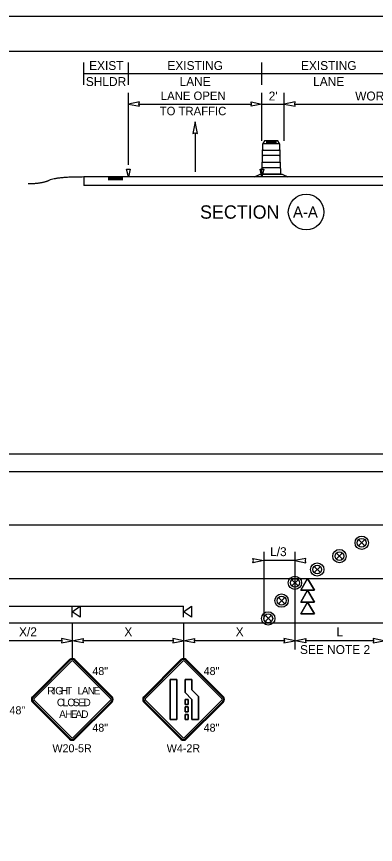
# Model space of a CAD drawing. Extents: x 99958 to 100136, y 99935 to 100013.
# Drawn here: x 100004.27 to 100007.5, y 100003.24 to 100010.69 of the extents above; entities that cross this region are included whole.
import ezdxf

# ---------------------------------------------------------------- set-up
doc = ezdxf.new("R2010")
doc.units = 0
for name, color, linetype in [('RD_ED_ShoulderPavedEdge', 7, 'Continuous'), ('RD_MK_LineEdgeWhite', 7, 'Continuous'), ('RD_MK_LineEdgeYellow', 7, 'Continuous'), ('RD_MK_LineLane', 7, 'Continuous'), ('SH_GI_PlotLimits', 7, 'Continuous'), ('SH_GI_SheetBorder', 7, 'Continuous'), ('SH_TI_WZSectionCut', 7, 'Continuous'), ('TR_SN_ConstructionSigns', 7, 'Continuous'), ('TR_WZ_ArrowLeftStrRightTurn', 7, 'Continuous'), ('TR_WZ_PortableSignMountBlk-Org', 7, 'Continuous'), ('TR_WZ_SequentialArrowSign', 7, 'Continuous'), ('TR_WZ_TrafficSafetyDrum', 7, 'Continuous'), ('TR_WZ_TrafficSafetyDrumElev', 7, 'Continuous'), ('TR_WZ_WorkZoneDetails', 7, 'Continuous'), ('TR_WZ_WorkZoneTextCurrent', 7, 'Continuous')]:
    doc.layers.add(name, color=color, linetype=linetype)

msp = doc.modelspace()

# ---------------------------------------------------------------- linework, layer by layer
at = {"layer": 'RD_ED_ShoulderPavedEdge'}
for p, q in [((100000.8283, 100006.7557), (100015.62, 100006.7557)), ((100000.8283, 100005.2357), (100015.62, 100005.2357))]:
    msp.add_line(p, q, dxfattribs=at)
at = {"layer": 'RD_MK_LineEdgeWhite'}
msp.add_line((100000.8283, 100005.6357), (100015.62, 100005.6357), dxfattribs=at)
at = {"layer": 'RD_MK_LineEdgeYellow'}
msp.add_line((100000.8283, 100006.5957), (100015.62, 100006.5957), dxfattribs=at)
at = {"layer": 'RD_MK_LineLane'}
msp.add_lwpolyline([(100015.62, 100006.1157), (100000.8283, 100006.1157)], dxfattribs=at)
at = {"layer": 'SH_GI_PlotLimits'}
msp.add_lwpolyline([(99999.0625, 99999.6875), (100016.0625, 99999.6875), (100016.0625, 100010.6875), (99999.0625, 100010.6875)], close=True, dxfattribs=at)
at = {"layer": 'SH_GI_SheetBorder'}
msp.add_line((100000, 100010.375), (100015.75, 100010.375), dxfattribs=at)
at = {"layer": 'SH_TI_WZSectionCut'}
for p, q in [((100004.8794, 100010.075), (100004.8794, 100010.275)), ((100005.2794, 100010.075), (100005.2794, 100010.275)), ((100006.4794, 100010.075), (100006.4794, 100010.275)), ((100004.8794, 100010.175), (100005.2794, 100010.175)), ((100005.2794, 100010.175), (100006.4794, 100010.175)), ((100006.4794, 100010.175), (100007.6794, 100010.175)), ((100005.2794, 100009.3547), (100005.2794, 100010.001)), ((100006.4794, 100009.57), (100006.4794, 100010.001)), ((100006.6794, 100009.57), (100006.6794, 100010.001)), ((100005.3731, 100009.901), (100006.3857, 100009.901)), ((100006.4794, 100009.901), (100006.6794, 100009.901)), ((100006.7731, 100009.901), (100008.5857, 100009.901)), ((100004.8794, 100009.2449), (100004.8794, 100009.1699)), ((100008.6794, 100009.2449), (100004.8794, 100009.2449)), ((100005.0964, 100009.2397), (100005.2294, 100009.2397)), ((100005.0964, 100009.2341), (100005.2294, 100009.2341)), ((100005.0964, 100009.2284), (100005.2294, 100009.2284)), ((100005.0964, 100009.2232), (100005.2294, 100009.2232)), ((100008.6794, 100009.1699), (100004.8794, 100009.1699))]:
    msp.add_line(p, q, dxfattribs=at)
for points in [[(100005.2794, 100009.901), (100005.3777, 100009.8817), (100005.3731, 100009.901), (100005.3777, 100009.9203)], [(100006.4794, 100009.901), (100006.3811, 100009.8817), (100006.3857, 100009.901), (100006.3811, 100009.9203)], [(100006.6794, 100009.901), (100006.7777, 100009.8817), (100006.7731, 100009.901), (100006.7777, 100009.9203)], [(100005.2627, 100009.3147), (100005.296, 100009.3147), (100005.2794, 100009.2449)], [(100006.4627, 100009.3147), (100006.4961, 100009.3147), (100006.4794, 100009.2449)]]:
    msp.add_lwpolyline(points, close=True, dxfattribs=at)
msp.add_circle((100006.8759, 100008.93), 0.16, dxfattribs=at)
msp.add_open_spline([(100004.8794, 100009.2449), (100004.6282, 100009.2449), (100004.5027, 100009.1828), (100004.3773, 100009.1828)], degree=2, dxfattribs=at)
at = {"layer": 'TR_SN_ConstructionSigns'}
for p, q in [((100004.7514, 100004.9058), (100004.4173, 100004.5717)), ((100004.7574, 100004.8999), (100004.4233, 100004.5658)), ((100005.1273, 100004.5658), (100004.7932, 100004.8999)), ((100005.1333, 100004.5717), (100004.7991, 100004.9058)), ((100005.7514, 100004.9058), (100005.4173, 100004.5717)), ((100005.7574, 100004.8999), (100005.4233, 100004.5658)), ((100006.1273, 100004.5658), (100005.7932, 100004.8999)), ((100006.1333, 100004.5717), (100005.7991, 100004.9058)), ((100004.4332, 100004.5558), (100004.7673, 100004.8899)), ((100004.7832, 100004.8899), (100005.1173, 100004.5558)), ((100005.4332, 100004.5558), (100005.7673, 100004.8899)), ((100005.7832, 100004.8899), (100006.1173, 100004.5558)), ((100005.6536, 100004.7279), (100005.7141, 100004.7279)), ((100005.6536, 100004.3679), (100005.6536, 100004.7279)), ((100005.7141, 100004.7279), (100005.6536, 100004.7279)), ((100005.6536, 100004.7279), (100005.6536, 100004.3679)), ((100005.7141, 100004.7279), (100005.7141, 100004.3679)), ((100005.7141, 100004.3679), (100005.7141, 100004.7279)), ((100005.7893, 100004.7279), (100005.8498, 100004.7279)), ((100005.7893, 100004.6083), (100005.7893, 100004.7279)), ((100005.8498, 100004.7279), (100005.7893, 100004.7279)), ((100005.7893, 100004.7279), (100005.7893, 100004.6083)), ((100005.8498, 100004.7279), (100005.8498, 100004.6334)), ((100005.8498, 100004.6334), (100005.8498, 100004.7279)), ((100005.8498, 100004.5479), (100005.7893, 100004.6083)), ((100005.7893, 100004.6083), (100005.8498, 100004.5479)), ((100005.8498, 100004.6334), (100005.9103, 100004.5729)), ((100005.9103, 100004.5729), (100005.8498, 100004.6334)), ((100004.4173, 100004.524), (100004.7514, 100004.1899)), ((100004.4233, 100004.53), (100004.7574, 100004.1959)), ((100004.7673, 100004.2058), (100004.4332, 100004.5399)), ((100005.1173, 100004.5399), (100004.7832, 100004.2058)), ((100004.7932, 100004.1959), (100005.1273, 100004.53)), ((100004.7991, 100004.1899), (100005.1333, 100004.524)), ((100005.4173, 100004.524), (100005.7514, 100004.1899)), ((100005.4233, 100004.53), (100005.7574, 100004.1959)), ((100005.7673, 100004.2058), (100005.4332, 100004.5399)), ((100006.1173, 100004.5399), (100005.7832, 100004.2058)), ((100005.7893, 100004.5479), (100005.8161, 100004.5479)), ((100005.7893, 100004.5029), (100005.7893, 100004.5479)), ((100005.8161, 100004.5479), (100005.7893, 100004.5479)), ((100005.7893, 100004.5479), (100005.7893, 100004.5029)), ((100005.7932, 100004.1959), (100006.1273, 100004.53)), ((100005.7991, 100004.1899), (100006.1333, 100004.524)), ((100005.8161, 100004.5479), (100005.8161, 100004.5029)), ((100005.8161, 100004.5029), (100005.8161, 100004.5479)), ((100005.8498, 100004.3679), (100005.8498, 100004.5479)), ((100005.8498, 100004.5479), (100005.8498, 100004.3679)), ((100005.9103, 100004.5729), (100005.9103, 100004.3679)), ((100005.9103, 100004.3679), (100005.9103, 100004.5729)), ((100005.8161, 100004.5029), (100005.7893, 100004.5029)), ((100005.7893, 100004.5029), (100005.8161, 100004.5029)), ((100005.7893, 100004.4804), (100005.8161, 100004.4804)), ((100005.7893, 100004.4354), (100005.7893, 100004.4804)), ((100005.8161, 100004.4804), (100005.7893, 100004.4804)), ((100005.7893, 100004.4804), (100005.7893, 100004.4354)), ((100005.8161, 100004.4804), (100005.8161, 100004.4354)), ((100005.8161, 100004.4354), (100005.8161, 100004.4804)), ((100005.8161, 100004.4354), (100005.7893, 100004.4354)), ((100005.7893, 100004.4354), (100005.8161, 100004.4354)), ((100005.7893, 100004.4129), (100005.8161, 100004.4129)), ((100005.7893, 100004.3679), (100005.7893, 100004.4129)), ((100005.8161, 100004.4129), (100005.7893, 100004.4129)), ((100005.7893, 100004.4129), (100005.7893, 100004.3679)), ((100005.8161, 100004.4129), (100005.8161, 100004.3679)), ((100005.8161, 100004.3679), (100005.8161, 100004.4129)), ((100005.7141, 100004.3679), (100005.6536, 100004.3679)), ((100005.6536, 100004.3679), (100005.7141, 100004.3679)), ((100005.8161, 100004.3679), (100005.7893, 100004.3679)), ((100005.7893, 100004.3679), (100005.8161, 100004.3679)), ((100005.9103, 100004.3679), (100005.8498, 100004.3679)), ((100005.8498, 100004.3679), (100005.9103, 100004.3679))]:
    msp.add_line(p, q, dxfattribs=at)
for centre, radius, start, end in [((100004.7753, 100004.882), 0.0338, 45, 135), ((100004.7753, 100004.882), 0.0253, 45, 135), ((100004.7753, 100004.882), 0.0113, 45, 135), ((100005.7753, 100004.882), 0.0338, 45, 135), ((100005.7753, 100004.882), 0.0253, 45, 135), ((100005.7753, 100004.882), 0.0113, 45, 135), ((100004.4412, 100004.5479), 0.0338, 135, 225.00001), ((100004.4412, 100004.5479), 0.0253, 135, 225.00001), ((100004.4412, 100004.5479), 0.0113, 135, 225.00001), ((100005.1094, 100004.5479), 0.0113, 315.00002, 45), ((100005.1094, 100004.5479), 0.0253, 315.00002, 45), ((100005.1094, 100004.5479), 0.0338, 315.00001, 45.00001), ((100005.4412, 100004.5479), 0.0338, 135, 225.00001), ((100005.4412, 100004.5479), 0.0253, 135, 225.00001), ((100005.4412, 100004.5479), 0.0113, 135, 225.00001), ((100006.1094, 100004.5479), 0.0113, 315.00002, 45), ((100006.1094, 100004.5479), 0.0253, 315.00002, 45), ((100006.1094, 100004.5479), 0.0338, 315.00001, 45.00001), ((100004.7753, 100004.2138), 0.0338, 225.00001, 315.00001), ((100004.7753, 100004.2138), 0.0253, 225.00001, 315.00002), ((100004.7753, 100004.2138), 0.0113, 225.00001, 315.00002), ((100005.7753, 100004.2138), 0.0338, 225.00001, 315.00001), ((100005.7753, 100004.2138), 0.0253, 225.00001, 315.00002), ((100005.7753, 100004.2138), 0.0113, 225.00001, 315.00002)]:
    msp.add_arc(centre, radius, start, end, dxfattribs=at)
at = {"layer": 'TR_WZ_ArrowLeftStrRightTurn'}
msp.add_line((100005.8794, 100009.6418), (100005.8794, 100009.292), dxfattribs=at)
msp.add_lwpolyline([(100005.8794, 100009.742), (100005.8588, 100009.6369), (100005.8794, 100009.6418), (100005.9, 100009.6369)], close=True, dxfattribs=at)
at = {"layer": 'TR_WZ_PortableSignMountBlk-Org'}
for p, q in [((100004.7753, 100005.2858), (100004.7753, 100005.3858)), ((100005.7753, 100005.2858), (100005.7753, 100005.3858))]:
    msp.add_line(p, q, dxfattribs=at)
for points in [[(100004.7753, 100005.3357), (100004.8471, 100005.3858), (100004.8471, 100005.2858)], [(100005.7753, 100005.3357), (100005.8471, 100005.3858), (100005.8471, 100005.2858)]]:
    msp.add_lwpolyline(points, close=True, dxfattribs=at)
at = {"layer": 'TR_WZ_SequentialArrowSign'}
for points in [[(100006.8895, 100005.6357), (100006.8278, 100005.5291), (100006.8895, 100005.5291), (100006.9513, 100005.5291), (100006.8895, 100005.6357)], [(100006.9513, 100005.5291), (100006.8895, 100005.5291), (100006.8278, 100005.5291), (100006.8895, 100005.6357), (100006.9513, 100005.5291)], [(100006.8895, 100005.5291), (100006.8278, 100005.4224), (100006.8895, 100005.4224), (100006.9513, 100005.4224), (100006.8895, 100005.5291)], [(100006.9513, 100005.4224), (100006.8895, 100005.4224), (100006.8278, 100005.4224), (100006.8895, 100005.5291), (100006.9513, 100005.4224)], [(100006.8895, 100005.4224), (100006.8278, 100005.3157), (100006.9513, 100005.3157), (100006.8895, 100005.4224)], [(100006.9513, 100005.3157), (100006.8278, 100005.3157), (100006.8895, 100005.4224), (100006.9513, 100005.3157)]]:
    msp.add_lwpolyline(points, dxfattribs=at)
at = {"layer": 'TR_WZ_TrafficSafetyDrum'}
for p, q in [((100007.347, 100005.984), (100007.4036, 100005.9274)), ((100007.4036, 100005.984), (100007.347, 100005.9274)), ((100007.147, 100005.864), (100007.2036, 100005.8074)), ((100007.2036, 100005.864), (100007.147, 100005.8074)), ((100006.947, 100005.744), (100007.0036, 100005.6874)), ((100007.0036, 100005.744), (100006.947, 100005.6874)), ((100006.747, 100005.624), (100006.8036, 100005.5674)), ((100006.8036, 100005.624), (100006.747, 100005.5674)), ((100006.627, 100005.464), (100006.6836, 100005.4074)), ((100006.6836, 100005.464), (100006.627, 100005.4074)), ((100006.507, 100005.304), (100006.5636, 100005.2474)), ((100006.5636, 100005.304), (100006.507, 100005.2474))]:
    msp.add_line(p, q, dxfattribs=at)
for centre, radius in [((100007.3753, 100005.9557), 0.06), ((100007.3753, 100005.9557), 0.06), ((100007.3753, 100005.9557), 0.04), ((100007.1753, 100005.8357), 0.06), ((100007.1753, 100005.8357), 0.06), ((100007.1753, 100005.8357), 0.04), ((100006.9753, 100005.7157), 0.06), ((100006.9753, 100005.7157), 0.06), ((100006.9753, 100005.7157), 0.04), ((100006.7753, 100005.5957), 0.06), ((100006.7753, 100005.5957), 0.06), ((100006.7753, 100005.5957), 0.04), ((100006.6553, 100005.4357), 0.06), ((100006.6553, 100005.4357), 0.06), ((100006.6553, 100005.4357), 0.04), ((100006.5353, 100005.2757), 0.06), ((100006.5353, 100005.2757), 0.06), ((100006.5353, 100005.2757), 0.04)]:
    msp.add_circle(centre, radius, dxfattribs=at)
at = {"layer": 'TR_WZ_TrafficSafetyDrumElev'}
for p, q in [((100006.4878, 100009.545), (100006.6358, 100009.545)), ((100006.4878, 100009.545), (100006.6358, 100009.545)), ((100006.5222, 100009.564), (100006.604, 100009.564)), ((100006.604, 100009.551), (100006.5222, 100009.551)), ((100006.4849, 100009.4871), (100006.6386, 100009.4871)), ((100006.4849, 100009.4372), (100006.4849, 100009.4871)), ((100006.6386, 100009.4372), (100006.4849, 100009.4372)), ((100006.6386, 100009.4871), (100006.6386, 100009.4372)), ((100006.4812, 100009.377), (100006.6423, 100009.377)), ((100006.4812, 100009.3271), (100006.4812, 100009.377)), ((100006.6423, 100009.377), (100006.6423, 100009.3271)), ((100006.6423, 100009.3271), (100006.4812, 100009.3271))]:
    msp.add_line(p, q, dxfattribs=at)
for points in [[(100006.4868, 100009.4915), (100006.4868, 100009.543)], [(100006.4868, 100009.4915), (100006.4868, 100009.543)], [(100006.6368, 100009.543), (100006.6368, 100009.4915)], [(100006.6368, 100009.543), (100006.6368, 100009.4915)], [(100006.4831, 100009.3814), (100006.4831, 100009.4327)], [(100006.4831, 100009.3814), (100006.4831, 100009.4327)], [(100006.4849, 100009.4365), (100006.4849, 100009.4878)], [(100006.4849, 100009.4365), (100006.4849, 100009.4878)], [(100006.6386, 100009.4878), (100006.6386, 100009.4365)], [(100006.6386, 100009.4878), (100006.6386, 100009.4365)], [(100006.6405, 100009.4327), (100006.6405, 100009.3814)], [(100006.6405, 100009.4327), (100006.6405, 100009.3814)], [(100006.4812, 100009.3264), (100006.4812, 100009.3777)], [(100006.4812, 100009.3264), (100006.4812, 100009.3777)], [(100006.6423, 100009.3777), (100006.6423, 100009.3264)], [(100006.6423, 100009.3777), (100006.6423, 100009.3264)], [(100006.6442, 100009.3226), (100006.6442, 100009.27), (100006.4794, 100009.27), (100006.4794, 100009.3226)], [(100006.6442, 100009.3226), (100006.6442, 100009.27), (100006.4794, 100009.27), (100006.4794, 100009.3226)]]:
    msp.add_lwpolyline(points, dxfattribs=at)
for points in [[(100006.6358, 100009.545), (100006.6226, 100009.57), (100006.5009, 100009.57), (100006.4878, 100009.545)], [(100006.4118, 100009.245), (100006.462, 100009.27), (100006.6615, 100009.27), (100006.7118, 100009.245)]]:
    msp.add_lwpolyline(points, close=True, dxfattribs=at)
for centre, major_axis, ratio, start_param, end_param in [((100006.488, 100009.5426), (0, 0.00249), 0.493438, 0.177149, 1.393647), ((100006.488, 100009.5426), (0, 0.00249), 0.493438, 0.177149, 1.393647), ((100006.5222, 100009.5575), (0, 0.0065), 0.570305, 0, 3.141593), ((100006.604, 100009.5575), (0, 0.0065), 0.570305, 3.141593, 6.283185), ((100006.6356, 100009.5426), (0, 0.00249), 0.493438, 4.889538, 6.106036), ((100006.6356, 100009.5426), (0, 0.00249), 0.493438, 4.889538, 6.106036), ((100006.4865, 100009.4296), (0, 0.00758), 0.493438, 0.4288, 1.141997), ((100006.4865, 100009.4296), (0, 0.00758), 0.493438, 0.4288, 1.141997), ((100006.4883, 100009.4846), (0, 0.00758), 0.493438, 0.4288, 1.141997), ((100006.4883, 100009.4846), (0, 0.00758), 0.493438, 0.4288, 1.141997), ((100006.6352, 100009.4846), (0, 0.00758), 0.493438, 5.141189, 5.854386), ((100006.6352, 100009.4846), (0, 0.00758), 0.493438, 5.141189, 5.854386), ((100006.6371, 100009.4296), (0, 0.00758), 0.493438, 5.141189, 5.854386), ((100006.6371, 100009.4296), (0, 0.00758), 0.493438, 5.141189, 5.854386), ((100006.4846, 100009.3745), (0, 0.00758), 0.493438, 0.4288, 1.141997), ((100006.4846, 100009.3745), (0, 0.00758), 0.493438, 0.4288, 1.141997), ((100006.6389, 100009.3745), (0, 0.00758), 0.493438, 5.141189, 5.854386), ((100006.6389, 100009.3745), (0, 0.00758), 0.493438, 5.141189, 5.854386), ((100006.4828, 100009.3195), (0, 0.00758), 0.493438, 0.4288, 1.141997), ((100006.4828, 100009.3195), (0, 0.00758), 0.493438, 0.4288, 1.141997), ((100006.6408, 100009.3195), (0, 0.00758), 0.493438, 5.141189, 5.854386), ((100006.6408, 100009.3195), (0, 0.00758), 0.493438, 5.141189, 5.854386)]:
    msp.add_ellipse(centre, major_axis=major_axis, ratio=ratio, start_param=start_param, end_param=end_param, dxfattribs=at)
at = {"layer": 'TR_WZ_WorkZoneDetails'}
for p, q in [((100006.4953, 100005.8757), (100006.4953, 100005.2757)), ((100006.7753, 100005.8757), (100006.7753, 100004.9957)), ((100006.7753, 100005.7957), (100006.4953, 100005.7957)), ((100003.2471, 100005.3858), (100005.7753, 100005.3858)), ((100004.7753, 100005.236), (100004.7753, 100004.9157)), ((100005.7753, 100005.236), (100005.7753, 100004.9157)), ((100004.6815, 100005.0757), (100004.069, 100005.0757)), ((100005.6815, 100005.0757), (100004.869, 100005.0757)), ((100006.6815, 100005.0757), (100005.869, 100005.0757)), ((100007.4815, 100005.0757), (100006.869, 100005.0757))]:
    msp.add_line(p, q, dxfattribs=at)
for points in [[(100006.4953, 100005.7957), (100006.397, 100005.7765), (100006.4016, 100005.7957), (100006.397, 100005.815)], [(100006.7753, 100005.7957), (100006.8736, 100005.7765), (100006.869, 100005.7957), (100006.8736, 100005.815)], [(100004.7753, 100005.0757), (100004.677, 100005.095), (100004.6815, 100005.0757), (100004.677, 100005.0565)], [(100004.7753, 100005.0757), (100004.8736, 100005.095), (100004.869, 100005.0757), (100004.8736, 100005.0565)], [(100005.7753, 100005.0757), (100005.677, 100005.095), (100005.6815, 100005.0757), (100005.677, 100005.0565)], [(100005.7753, 100005.0757), (100005.8736, 100005.095), (100005.869, 100005.0757), (100005.8736, 100005.0565)], [(100006.7753, 100005.0757), (100006.677, 100005.095), (100006.6815, 100005.0757), (100006.677, 100005.0565)], [(100006.7753, 100005.0757), (100006.8736, 100005.095), (100006.869, 100005.0757), (100006.8736, 100005.0565)], [(100007.5753, 100005.0757), (100007.477, 100005.095), (100007.4815, 100005.0757), (100007.477, 100005.0565)]]:
    msp.add_lwpolyline(points, close=True, dxfattribs=at)

# ---------------------------------------------------------------- texts
at = {"layer": 'SH_TI_WZSectionCut'}
for s, height, p in [('EXIST', 0.08, (100004.9261, 100010.207)), ('EXISTING', 0.08, (100005.6296, 100010.207)), ('EXISTING', 0.08, (100006.8296, 100010.207)), ('SHLDR', 0.08, (100004.8969, 100010.063)), ('LANE', 0.08, (100005.739, 100010.063)), ('LANE', 0.08, (100006.939, 100010.063)), ('SECTION', 0.12, (100005.9229, 100008.87)), ('A-A', 0.1, (100006.7581, 100008.88))]:
    msp.add_text(s, height=height, rotation=360, dxfattribs=at).set_placement(p)
for s, height, p in [('LANE OPEN', 0.076, (100005.5707, 100009.937)), ("2'", 0.08, (100006.5394, 100009.933)), ('WORK AREA', 0.08, (100007.3165, 100009.933)), ('TO TRAFFIC', 0.076, (100005.5606, 100009.8002))]:
    msp.add_text(s, height=height, dxfattribs=at).set_placement(p)
at = {"layer": 'TR_SN_ConstructionSigns'}
for s, p in [('48"', (100004.9551, 100004.7664)), ('48"', (100005.9551, 100004.7664)), ('48"', (100004.211, 100004.414)), ('48"', (100004.9551, 100004.2573)), ('48"', (100005.9551, 100004.2573)), ('W20-5R', (100004.5966, 100004.072)), ('W4-2R', (100005.6238, 100004.072))]:
    msp.add_text(s, height=0.072, rotation=360, dxfattribs=at).set_placement(p)
for s, p in [('R', (100004.5498, 100004.5922)), ('I', (100004.5991, 100004.5922)), ('G', (100004.6221, 100004.5922)), ('H', (100004.6734, 100004.5922)), ('T', (100004.7206, 100004.5922)), ('L', (100004.8225, 100004.5922)), ('A', (100004.861, 100004.5922)), ('N', (100004.9137, 100004.5922)), ('E', (100004.9663, 100004.5922)), ('C', (100004.6369, 100004.4867)), ('L', (100004.6882, 100004.4867)), ('O', (100004.7307, 100004.4867)), ('S', (100004.7807, 100004.4867)), ('E', (100004.83, 100004.4867)), ('D', (100004.8759, 100004.4867)), ('A', (100004.6572, 100004.3812)), ('H', (100004.7098, 100004.3812)), ('E', (100004.7625, 100004.3812)), ('A', (100004.803, 100004.3812)), ('D', (100004.8556, 100004.3812))]:
    msp.add_text(s, height=0.0675, dxfattribs=at).set_placement(p)
at = {"layer": 'TR_WZ_WorkZoneTextCurrent'}
msp.add_text('L/3', height=0.08, dxfattribs=at).set_placement((100006.5521, 100005.8357))
for s, p in [('X/2', (100004.2968, 100005.1157)), ('X', (100005.2428, 100005.1157)), ('X', (100006.2428, 100005.1157)), ('L', (100007.1481, 100005.1157)), ('SEE NOTE 2', (100006.8206, 100004.9557))]:
    msp.add_text(s, height=0.08, rotation=360, dxfattribs=at).set_placement(p)

doc.saveas('drawing.dxf')
